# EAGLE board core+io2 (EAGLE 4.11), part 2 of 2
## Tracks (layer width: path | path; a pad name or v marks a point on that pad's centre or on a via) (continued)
N$113 (continued)
  Top 0.254: IC14.19 99.05,110.33 97.78,111.59 97.78,114.77 99.69,116.67 SV7.15
N$114  (via drill 0.61)
  Top 0.254: v96.52,102.07 97.15,102.7 97.15,116.67 SV7.13
  Bottom 0.254: v96.52,102.07 98.42,102.07 IC14.16
N$115  (via drill 0.61)
  Top 0.254: v100.96,118.58 103.5,121.12 106.67,121.12 v106.67,100.8
  Bottom 0.254: v100.96,118.58 95.24,118.58 94.61,117.94 SV7.11 | v106.67,100.8 102.23,100.8 101.59,100.16 100.32,100.16 IC14.15
N$116  (via drill 0.61)
  Top 0.254: v97.78,83.66 97.78,91.28 98.42,91.91 IC14.12 | v116.2,80.48 116.2,87.47 117.47,88.73 117.47,115.41 v116.83,116.04
  Bottom 0.254: v97.78,83.66 100.32,81.11 106.67,81.11 107.31,80.48 107.94,80.48 108.58,79.84 114.3,79.84 114.93,80.48 v116.2,80.48 | v116.83,116.04 116.2,116.67 106.67,116.67 106.04,116.04 92.7,116.04 92.07,116.67 SV7.9
N$117
  Top 0.254: IC14.2 91.44,110.33 90.16,111.59 90.16,116.04 90.8,116.67 90.8,117.94 92.07,119.22 SV7.10
N$118  (via drill 0.61)
  Top 0.254: v102.23,103.34 v102.23,111.59 | v95.88,113.5 95.88,117.94 95.24,118.58 95.24,119.85 SV7.12
  Bottom 0.254: v102.23,103.34 93.34,103.34 92.7,102.7 IC14.5 | v102.23,111.59 101.59,112.23 101.59,113.5 v95.88,113.5
N$119  (via drill 0.61)
  Top 0.254: v59.05,101.44 59.05,106.52 58.41,107.15 58.41,114.77 60.32,116.67 v60.32,122.39 | v85.72,123.03 88.26,125.56 97.15,125.56 97.15,120.48 SV7.14
  Bottom 0.254: v59.05,101.44 59.69,101.44 60.32,100.8 67.94,100.8 68.57,101.44 72.38,101.44 73.02,100.8 80.64,100.8 81.27,101.44 85.08,101.44 85.72,100.8 88.26,100.8 88.89,100.16 91.44,100.16 IC14.6 | v60.32,122.39 66.67,122.39 67.94,123.66 69.21,122.39 85.08,122.39 v85.72,123.03
N$120  (via drill 0.61)
  Top 0.254: v109.21,93.18 108.58,93.81 108.58,101.44 107.94,102.07 107.94,117.94 v108.58,118.58
  Bottom 0.254: v109.21,93.18 94.61,93.18 93.97,92.55 92.7,92.55 IC14.9 | v108.58,118.58 103.5,118.58 102.23,119.85 100.32,119.85 SV7.16
N$121  (via drill 0.61)
  Top 0.254: v85.72,118.58 85.72,113.5 85.08,112.86 85.08,92.55 v84.45,91.91
  Bottom 0.254: v85.72,118.58 88.89,118.58 89.53,119.22 SV7.8 | v84.45,91.91 80.64,91.91 IC13.9
N$122  (via drill 0.61)
  Top 0.254: v78.1,85.56 78.1,86.19 77.46,86.83 77.46,98.89 78.1,99.53 IC13.6 | v110.48,85.56 v110.48,123.03 | v86.99,123.03 86.99,120.48 SV7.6
  Bottom 0.254: v78.1,85.56 92.07,85.56 92.7,86.19 101.59,86.19 102.23,85.56 v110.48,85.56 | v110.48,123.03 107.94,123.03 107.31,122.39 87.62,122.39 v86.99,123.03
N$123
  Top 0.254: IC13.5 80,102.7 81.27,103.97 81.27,107.15 82.55,108.42 81.91,109.05 81.91,113.5 80.64,114.77 80.64,122.39 83.18,124.93 84.45,124.93 84.45,120.48 SV7.4
N$124  (via drill 0.61)
  Top 0.254: v56.51,50.63 56.51,36.03 55.24,34.76 52.7,34.76 51.43,36.03 51.43,36.66 50.8,37.3 50.8,39.2 50.16,39.84 v50.16,43.02 | v42.54,44.28 42.54,49.37 41.27,50.63 41.27,67.14 40,68.41 v40,70.32
  Bottom 0.254: v56.51,50.63 57.15,51.27 62.86,51.27 64.13,50 76.83,50 78.73,51.91 79.37,51.27 80.64,51.27 IC24.13 | v50.16,43.02 48.89,44.28 v42.54,44.28 | v40,70.32 45.72,70.32 46.98,69.05 47.62,69.05 IC26.5
N$125  (via drill 0.61)
  Top 0.254: v30.47,67.78 31.11,67.14 v31.11,46.19 | v79.37,46.82 80.64,48.09 80.64,48.73 IC24.14
  Bottom 0.254: v30.47,67.78 46.35,67.78 46.98,67.14 48.26,67.14 IC26.6 | v31.11,46.19 31.74,46.82 v79.37,46.82
N$126  (via drill 0.61)
  Top 0.254: v59.69,45.55 v59.69,57.62 | v50.8,57.62 50.8,63.34 50.16,63.97 IC26.7
  Bottom 0.254: v59.69,45.55 60.32,46.19 78.1,46.19 79.37,44.92 80,45.55 81.27,45.55 IC24.15 | v59.69,57.62 v50.8,57.62
N$127  (via drill 0.61)
  Top 0.254: v78.73,44.28 79.37,43.65 80.64,43.65 IC24.16 | v53.34,43.65 53.97,44.28 v53.97,63.97
  Bottom 0.254: v78.73,44.28 78.1,43.65 70.48,43.65 69.84,44.28 68.57,43.02 53.97,43.02 v53.34,43.65 | v53.97,63.97 53.34,63.34 52.07,63.34 50.8,62.06 49.53,62.06 IC26.8
N$128  (via drill 0.61)
  Top 0.254: v46.98,50.63 46.98,58.25 47.62,58.89 IC26.9 | v72.38,51.27 71.75,50.63 v71.75,41.11
  Bottom 0.254: v46.98,50.63 47.62,51.27 53.34,51.27 53.97,51.91 66.03,51.91 67.3,50.63 71.75,50.63 v72.38,51.27 | v71.75,41.11 80.64,41.11 IC24.17
N$129
  Bottom 0.254: IC25.3 68.57,74.77 67.3,76.03 67.3,77.94 78.1,77.94 79.37,76.67 80.64,76.67 IC24.3
N$130
  Bottom 0.254: IC25.4 70.48,71.59 71.75,72.86 78.73,72.86 80,74.13 80.64,74.13 IC24.4
N$131
  Bottom 0.254: IC25.5 70.48,69.05 71.75,70.32 79.37,70.32 80.64,71.59 IC24.5
N$132
  Bottom 0.254: IC25.6 70.48,66.51 71.75,67.78 79.37,67.78 80.64,69.05 IC24.6
N$133
  Bottom 0.254: IC25.7 70.48,63.97 71.75,62.7 83.18,62.7 83.81,63.34 83.81,65.88 82.55,65.88 IC24.7
N$134  (via drill 0.61)
  Top 0.254: v73.02,61.43 v73.02,65.24
  Bottom 0.254: v73.02,61.43 70.48,61.43 IC25.8 | v73.02,65.24 78.1,65.24 79.37,63.97 80.64,63.97 IC24.8
N$135
  Bottom 0.254: IC25.9 70.48,58.89 71.75,58.89 72.38,59.52 74.92,59.52 75.56,60.16 78.73,60.16 80,61.43 80.64,61.43 IC24.9
N$136  (via drill 0.61)
  Top 0.254: v43.81,39.2 43.81,49.37 v42.54,50.63 | v18.41,50.63 v18.41,81.75
  Bottom 0.254: v43.81,39.2 44.45,38.57 45.72,38.57 46.98,39.84 67.94,39.84 70.48,37.3 77.46,37.3 78.1,36.66 81.27,36.66 IC24.19 | v42.54,50.63 41.91,51.27 23.49,51.27 22.86,50.63 v18.41,50.63 | v18.41,81.75 19.68,83.02 29.84,83.02 30.47,82.39 41.27,82.39 41.91,83.02 45.72,83.02 48.89,79.84 IC26.1
N$137
  Bottom 0.254: IC25.1 70.48,79.21 74.29,79.21 75.56,80.48 83.18,80.48 84.45,79.21 95.88,79.21 IC24.39
N$138  (via drill 0.61)
  Top 0.254: v92.07,81.11 92.07,71.59 92.7,70.95 92.7,40.48 90.8,38.57 90.8,37.3 91.44,36.66 91.44,24.6 v90.8,23.96 | v99.69,23.96 99.69,16.98 100.32,16.34 v100.32,11.9
  Bottom 0.254: v92.07,81.11 92.7,81.75 95.88,81.75 IC24.40 | v99.69,23.96 v90.8,23.96 | v100.32,11.9 108.58,11.9 109.21,11.27 113.02,11.27 113.66,11.9 118.1,11.9 119.38,13.17 121.28,13.17 IC27.9
N$140
  Top 0.254: IC27.8 123.82,10.63 124.45,10.63 C4.1 | IC27.12 123.19,20.15 129.53,13.81 129.53,13.17 R4.1
  Bottom 0.254: R4.1 129.53,13.17 126.99,10.63 125.72,10.63 C4.1
N$141
  Top 0.254: R3.1 128.27,20.79 129.53,20.79 R4.2
  Bottom 0.254: IC27.13 123.19,22.7 123.82,22.06 125.72,22.06 126.99,20.79 R3.1
N$142
  Bottom 0.254: IC27.11 123.82,18.25 132.07,18.25 C5.1
N$143
  Bottom 0.254: R10.1 114.3,5.55 113.02,6.82 112.39,6.82 R11.E
N$144  (via drill 0.61)
  Top 0.254: v86.35,16.34 86.35,18.88 86.99,19.52 88.89,19.52 88.89,20.15 X1.4
  Bottom 0.254: v86.35,16.34 94.61,16.34 95.88,17.61 X1.6
N$145
  Top 0.254: X1.8 91.44,18.25 92.7,18.25 X1.7
N$146
  Bottom 0.254: 90.8,19.52 102.23,19.52 X1.G1 | 90.8,19.52 87.62,19.52 86.99,20.15 X1.5 | 90.8,19.52 90.8,21.42 88.89,23.33 83.81,23.33 81.27,20.79 X1.G2
N$147  (via drill 0.61)
  Top 0.254: IC18.13 153.03,20.15 153.03,18.88 IC18.12 | v100.96,34.76 100.96,36.66 99.05,38.57 99.05,53.17 100.32,54.45 100.32,60.8 100.96,61.43 IC21.5 | v149.85,32.22 v149.85,20.79
  Bottom 0.254: v100.96,34.76 110.48,34.76 112.39,36.66 122.55,36.66 125.72,33.49 125.72,31.58 146.04,31.58 146.68,32.22 v149.85,32.22 | v149.85,20.79 151.76,20.79 IC18.13
N$148
  Top 0.254: IC18.11 154.3,15.71 154.94,15.71 LED1.K
N$149
  Bottom 0.254: R12.1 125.72,20.79 126.99,19.52 154.94,19.52 158.11,16.34 LED1.A
N$150  (via drill 0.61)
  Top 0.254: v118.74,77.94 118.74,71.59 IC21.24 | v123.19,71.59 123.19,67.78 123.82,67.14 123.82,46.82 123.19,46.19 123.19,42.38 125.09,40.48 125.09,23.96 R13.2
  Bottom 0.254: v118.74,77.94 v113.66,77.94 112.39,79.21 106.04,79.21 JP2.1 | v123.19,71.59 118.74,71.59 IC21.24
N$151
  Bottom 0.254: IC18.8 151.76,8.09 150.49,9.36 144.14,9.36 143.5,10 143.5,14.44 158.75,14.44 163.19,18.88 163.19,63.97 158.11,63.97 156.84,62.7 150.49,62.7 149.22,61.43 IC28.4
N$152
  Top 0.254: IC19.5 148.59,36.66 152.39,40.48 152.39,45.55 157.47,50.63 157.47,64.61 156.2,65.88 IC28.15
N$153
  Top 0.254: IC20.7 118.1,30.31 119.38,30.31 IC20.8
N$154
  Bottom 0.254: C7.1 109.85,25.23 112.39,22.7 113.02,22.7 114.3,21.42 IC27.3
N$155
  Top 0.254: IC20.5 113.02,31.58 118.1,36.66 121.91,36.66 121.91,38.57 C9.2
N$156
  Bottom 0.254: IC20.4 110.48,31.58 112.39,33.49 121.91,33.49 C9.1
N$157  (via drill 0.61)
  Top 0.254: v106.67,36.03 106.67,31.58 IC20.3
  Bottom 0.254: v106.67,36.03 100.32,36.03 C8.2
N$158
  Top 0.254: C8.1 100.32,30.95 101.59,30.95 IC20.1
N$159
  Bottom 0.254: C11.1 110.48,28.41 111.12,29.04 113.02,29.04 114.3,30.31 IC20.6
N$160
  Top 0.254: C10.2 102.86,28.41 104.13,29.68 104.13,30.31 IC20.2
NMI\  (via drill 0.61)
  Top 0.254: IC17.6 126.36,69.05 125.09,70.32 125.09,73.5 R6.1 | v114.93,55.71 v114.93,67.78
  Bottom 0.254: v114.93,55.71 102.86,55.71 IC21.7 | v114.93,67.78 121.91,67.78 123.19,69.05 126.36,69.05 IC17.6
OUT00  (via drill 0.61)
  Top 0.254: v10.79,86.83 10.79,88.73 IC6.11 | v28.57,87.47 28.57,82.39 IC1.1
  Bottom 0.254: v10.79,86.83 11.43,87.47 v28.57,87.47
OUT01  (via drill 0.61)
  Top 0.254: v25.39,79.21 23.49,81.11 23.49,88.73 IC7.11
  Bottom 0.254: v25.39,79.21 27.3,79.21 IC1.2
OUT02
  Bottom 0.254: IC1.3 27.3,76.67 26.66,76.03 22.86,76.03 22.22,75.4 14.6,75.4 6.98,83.02 5.08,83.02 1.27,86.83 1.27,90.64 33.65,90.64 34.92,89.37 IC8.11
OUT03  (via drill 0.61)
  Top 0.254: v30.47,87.47 30.47,74.77 29.84,74.13 IC1.4
  Bottom 0.254: v30.47,87.47 42.54,87.47 44.45,89.37 47.62,89.37 IC10.11
OUT04  (via drill 0.61)
  Top 0.254: v25.39,71.59 25.39,77.94 22.86,80.48 22.86,83.02 v20.31,85.56 | v59.69,84.29 61.59,86.19 61.59,88.73 IC11.11
  Bottom 0.254: v25.39,71.59 27.3,71.59 IC1.5 | v20.31,85.56 20.95,84.92 21.58,84.92 22.22,85.56 31.11,85.56 31.74,86.19 42.54,86.19 43.18,85.56 56.51,85.56 57.78,84.29 v59.69,84.29
OUT05  (via drill 0.61)
  Top 0.254: v43.18,93.18 43.18,83.66 41.27,81.75 v41.27,69.05
  Bottom 0.254: v43.18,93.18 55.88,93.18 55.88,91.28 56.51,90.64 57.15,90.64 57.78,91.28 59.69,91.28 60.32,90.64 68.57,90.64 69.84,89.37 73.02,89.37 IC12.11 | v41.27,69.05 40.64,68.41 31.11,68.41 30.47,69.05 29.84,69.05 IC1.6
OUT06  (via drill 0.61)
  Top 0.254: v86.35,60.16 86.35,84.29 86.99,84.92 86.99,88.73 IC13.11 | v80,60.16 79.37,59.52 v79.37,52.54 | v33.65,54.45 33.65,38.57 32.38,37.3 30.47,37.3 30.47,45.55 29.84,46.19 29.84,46.82 30.47,47.46 30.47,66.51 29.84,66.51 IC1.7
  Bottom 0.254: v80,60.16 v86.35,60.16 | v79.37,52.54 78.73,53.17 52.7,53.17 52.07,52.54 40.64,52.54 38.73,54.45 v33.65,54.45
OUT07  (via drill 0.61)
  Top 0.254: v33.02,63.97 33.65,64.61 33.65,79.84 v33.02,80.48 | v46.98,80.48 v46.98,87.47
  Bottom 0.254: v33.02,63.97 29.84,63.97 IC1.8 | v33.02,80.48 33.02,81.11 41.91,81.11 42.54,80.48 v46.98,80.48 | v46.98,87.47 47.62,86.83 56.51,86.83 57.15,87.47 57.78,87.47 59.05,86.19 61.59,86.19 62.23,85.56 72.38,85.56 73.66,86.83 78.1,86.83 78.73,86.19 81.91,86.19 83.18,87.47 92.7,87.47 94.61,89.37 98.42,89.37 IC14.11
PIA-A0  (via drill 0.61)
  Top 0.254: v72.38,80.48 v72.38,74.13 | IC6.3 1.9,107.15 1.27,106.52 1.27,36.66 1.9,36.03 IC2.2 4.44,36.03 5.08,36.66 v5.08,45.55 | v13.97,46.19 13.97,36.66 14.6,36.03 IC3.2 | v52.7,80.48 52.7,86.19 52.07,86.83 52.07,106.52 52.7,107.15 IC11.3 | v27.93,46.19 27.3,45.55 27.3,41.11 26.66,40.48 26.66,36.66 27.3,36.03 IC4.2
  Bottom 0.254: IC4.2 29.84,36.03 31.74,36.03 33.02,34.76 37.46,34.76 38.73,36.03 40,36.03 IC9.2 42.54,36.03 44.45,36.03 45.08,35.39 46.98,35.39 47.62,34.76 52.7,34.76 53.34,35.39 IC15.2 55.24,36.03 57.15,36.03 57.78,35.39 59.69,35.39 60.32,34.76 65.4,34.76 66.03,35.39 IC16.2 | v72.38,74.13 75.56,74.13 IC25.18 | v72.38,80.48 71.75,81.11 62.86,81.11 | 62.86,81.11 61.59,79.84 SV9.1 | 80.64,105.88 80,106.52 IC13.3 | 80.64,105.88 88.26,105.88 89.53,107.15 90.8,107.15 IC14.3 | IC6.3 3.8,106.52 4.44,105.88 12.06,105.88 12.7,106.52 13.33,106.52 13.97,107.15 14.6,107.15 IC7.3 17.14,107.15 19.04,107.15 19.68,106.52 21.58,106.52 22.22,105.88 27.3,105.88 27.93,106.52 IC8.3 29.84,107.15 33.65,107.15 34.92,105.88 37.46,105.88 38.1,106.52 40.64,106.52 IC10.3 42.54,107.15 44.45,107.15 45.08,106.52 46.98,106.52 47.62,105.88 52.7,105.88 53.34,106.52 IC11.3 55.24,107.15 57.15,107.15 57.78,106.52 59.69,106.52 60.32,105.88 65.4,105.88 66.03,106.52 IC12.3 67.94,107.15 69.84,107.15 71.11,105.88 80.64,105.88 | 13.33,45.55 v13.97,46.19 | v5.08,45.55 13.33,45.55 | 62.86,81.11 55.88,81.11 55.24,80.48 v52.7,80.48 | v27.93,46.19 27.3,45.55 13.33,45.55
PIA-A1  (via drill 0.61)
  Top 0.254: v74.92,84.29 74.92,72.22 75.56,71.59 IC25.17 | v60.96,84.29 60.32,83.66 60.32,77.3 60.96,76.67 SV9.3 | v87.62,84.29 87.62,87.47 88.89,88.73 88.89,98.26 89.53,98.89 89.53,103.34 90.8,104.61 IC14.4 | v72.38,27.14 72.38,39.2 73.66,40.48 73.66,55.08 73.02,55.71 73.02,60.16 71.75,61.43 v71.75,71.59
  Bottom 0.254: IC2.5 3.8,27.77 4.44,27.14 12.06,27.14 12.7,27.77 13.33,27.77 13.97,28.41 14.6,28.41 IC3.5 16.5,27.77 21.58,27.77 22.22,27.14 24.76,27.14 25.39,27.77 27.93,27.77 IC4.5 29.2,27.77 34.29,27.77 34.92,27.14 37.46,27.14 38.1,27.77 38.73,27.77 39.37,28.41 40,28.41 IC9.5 41.91,27.77 46.98,27.77 47.62,27.14 50.16,27.14 50.8,27.77 51.43,27.77 52.07,28.41 52.7,28.41 IC15.5 54.61,27.77 59.69,27.77 60.32,27.14 62.86,27.14 63.5,27.77 66.03,27.77 IC16.5 67.3,27.77 70.48,27.77 71.11,27.14 v72.38,27.14 | IC6.4 3.8,103.97 4.44,103.34 12.06,103.34 13.33,104.61 14.6,104.61 IC7.4 16.5,103.97 17.14,103.34 24.76,103.34 26.03,104.61 27.3,104.61 IC8.4 29.2,103.97 29.84,103.34 37.46,103.34 38.73,104.61 40,104.61 IC10.4 41.91,103.97 42.54,103.34 50.16,103.34 51.43,104.61 52.7,104.61 IC11.4 54.61,103.97 55.24,103.34 62.86,103.34 64.13,104.61 65.4,104.61 IC12.4 67.3,103.97 67.94,103.34 75.56,103.34 76.83,104.61 78.1,104.61 IC13.4 80.64,104.61 82.55,104.61 83.81,103.34 90.8,103.34 91.44,103.97 IC14.4 | v60.96,84.29 v74.92,84.29 75.56,83.66 86.99,83.66 v87.62,84.29 | v71.75,71.59 75.56,71.59 IC25.17
PIA-A2
  Top 0.254: SV9.5 61.59,73.5 60.32,72.22 60.32,70.95 60.96,70.32 65.4,70.32 65.4,88.1 64.77,88.73 64.77,95.08 66.03,96.36 IC12.7 | IC25.16 77.46,69.69 78.73,70.95 78.73,76.03 79.37,76.67 79.37,81.11 80,81.75 80,87.47 81.27,88.73 81.27,95.08 80,96.36 IC13.7 | IC4.6 27.93,26.5 26.66,27.77 26.66,35.39 26.03,36.03 26.03,70.95 26.66,71.59 26.66,95.08 27.93,96.36 IC8.7
  Bottom 0.254: IC16.6 65.4,25.87 64.13,24.6 56.51,24.6 55.24,25.87 IC15.6 52.7,25.87 51.43,24.6 45.72,24.6 44.45,25.87 42.54,25.87 IC9.6 40,25.87 38.73,24.6 33.65,24.6 33.02,25.23 29.2,25.23 IC4.6 27.3,25.87 26.03,25.87 24.76,24.6 13.33,24.6 | 13.33,24.6 5.71,24.6 4.44,25.87 IC2.6 | 13.33,24.6 14.6,25.87 IC3.6 | IC6.7 4.44,96.99 5.71,95.72 13.33,95.72 14.6,96.99 IC7.7 17.14,96.99 17.77,96.36 21.58,96.36 22.22,95.72 24.76,95.72 26.03,96.99 27.3,96.99 IC8.7 29.84,96.99 30.47,96.36 34.29,96.36 34.92,95.72 37.46,95.72 38.73,96.99 40,96.99 IC10.7 42.54,96.99 43.18,96.36 46.98,96.36 47.62,95.72 50.16,95.72 51.43,96.99 52.7,96.99 IC11.7 55.24,96.99 56.51,95.72 62.86,95.72 63.5,96.36 66.03,96.36 IC12.7 67.94,96.99 68.57,96.36 72.38,96.36 73.02,95.72 75.56,95.72 76.19,96.36 78.73,96.36 IC13.7 80,96.36 82.55,96.36 83.18,95.72 88.26,95.72 88.89,96.36 90.16,96.36 90.8,96.99 IC14.7
PIA-A3  (via drill 0.61)
  Top 0.254: v72.38,93.18 72.38,85.56 74.29,83.66 74.29,71.59 74.92,70.95 74.92,67.14 75.56,66.51 IC25.15 | v63.5,93.18 63.5,88.73 62.86,88.1 v62.86,82.39 62.86,72.22 62.23,71.59 SV9.7 | v50.8,81.75 50.8,78.58 50.16,77.94 46.98,77.94 46.98,79.21 45.72,80.48 v45.72,94.45 | IC9.9 42.54,18.25 43.81,16.98 v43.81,15.71 42.54,14.44 42.54,6.18 40.64,4.28 40.64,3.01 40,2.38 34.29,2.38 34.29,3.01 v33.65,3.64 | v7.62,16.98 8.25,17.61 8.25,27.14 8.89,27.77 8.89,39.2 10.16,40.48 10.16,41.74 10.79,42.38 10.79,47.46 13.33,50 13.33,53.81 12.7,54.45 12.7,68.41 13.33,69.05 13.33,69.69 12.7,70.32 12.7,79.84 13.33,80.48 v13.33,93.81 | v22.22,3.64 22.22,11.9 20.31,13.81 v20.31,16.98
  Bottom 0.254: 62.86,93.18 60.32,93.18 59.69,93.81 54.61,93.81 IC11.8 | 62.86,93.18 64.13,94.45 65.4,94.45 IC12.8 67.94,94.45 69.84,94.45 71.11,93.18 v72.38,93.18 78.1,93.18 78.73,93.81 IC13.8 80.64,94.45 81.91,94.45 83.18,93.18 90.8,93.18 91.44,93.81 IC14.8 | v63.5,93.18 62.86,93.18 | v62.86,82.39 51.43,82.39 v50.8,81.75 | v45.72,94.45 42.54,94.45 IC10.8 40.64,93.81 40,93.18 31.74,93.18 30.47,94.45 29.84,94.45 IC8.8 27.93,93.81 27.3,93.18 19.04,93.18 17.77,94.45 17.14,94.45 IC7.8 14.6,94.45 13.33,94.45 12.7,93.81 | v43.81,15.71 44.45,16.34 45.72,16.34 46.35,16.98 50.16,16.98 51.43,18.25 52.7,18.25 IC15.9 55.24,18.25 57.15,18.25 57.78,17.61 59.69,17.61 60.32,16.98 65.4,16.98 66.03,17.61 IC16.9 | IC2.9 3.8,17.61 4.44,16.98 v7.62,16.98 12.06,16.98 12.7,17.61 13.33,17.61 13.97,18.25 14.6,18.25 IC3.9 17.14,18.25 19.04,18.25 19.68,17.61 20.31,17.61 | 20.31,17.61 21.58,17.61 22.22,16.98 27.3,16.98 27.93,17.61 IC4.9 | 12.7,93.81 12.06,93.18 6.34,93.18 5.71,93.81 3.8,93.81 IC6.8 | v13.33,93.81 12.7,93.81 | v33.65,3.64 33.02,3.01 22.86,3.01 v22.22,3.64 | 20.31,17.61 v20.31,16.98
PIA-A4  (via drill 0.61)
  Top 0.254: v71.11,94.45 71.11,93.18 71.75,92.55 71.75,84.92 73.66,83.02 73.66,70.95 74.29,70.32 74.29,66.51 74.92,65.88 74.92,64.61 75.56,63.97 IC25.14 | v65.4,65.24 65.4,67.78 63.5,67.78 62.23,69.05 SV9.9 | v6.98,22.06 7.62,22.7 7.62,27.77 8.25,28.41 8.25,39.84 9.52,41.11 9.52,42.38 10.16,43.02 10.16,78.58 8.89,79.84 8.89,93.81 9.52,94.45 IC6.13
  Bottom 0.254: IC12.13 74.92,95.08 76.19,95.08 76.83,95.72 81.91,95.72 82.55,95.08 86.35,95.08 IC13.13 87.62,95.08 88.89,95.08 89.53,95.72 93.34,95.72 94.61,94.45 98.42,94.45 IC14.13 | IC12.13 73.66,95.08 72.38,95.08 71.75,95.72 64.13,95.72 63.5,95.08 62.23,95.08 IC11.13 60.32,94.45 56.51,94.45 55.24,95.72 51.43,95.72 50.8,95.08 49.53,95.08 IC10.13 48.26,95.08 46.98,95.08 46.35,95.72 38.73,95.72 38.1,95.08 36.83,95.08 IC8.13 35.55,95.08 34.29,95.08 33.65,95.72 26.03,95.72 25.39,95.08 24.12,95.08 IC7.13 22.86,95.08 21.58,95.08 20.95,95.72 14.6,95.72 13.97,95.08 11.43,95.08 IC6.13 | v71.11,94.45 73.02,94.45 IC12.13 | v65.4,65.24 70.48,65.24 71.11,64.61 72.38,64.61 73.02,63.97 75.56,63.97 IC25.14 | IC16.12 73.66,18.88 71.75,18.88 71.11,19.52 65.4,19.52 64.77,18.88 62.23,18.88 IC15.12 60.32,18.25 58.41,18.25 57.78,18.88 55.88,18.88 55.24,19.52 50.16,19.52 49.53,18.88 IC9.12 47.62,18.25 46.35,18.25 45.08,16.98 40,16.98 38.73,18.25 37.46,18.25 IC4.12 34.92,18.25 33.02,18.25 32.38,18.88 30.47,18.88 29.84,19.52 27.3,19.52 26.66,18.88 24.12,18.88 IC3.12 22.22,18.25 20.31,18.25 19.04,19.52 13.97,19.52 | 13.97,19.52 12.7,18.25 12.06,18.25 IC2.12 | 13.97,19.52 12.7,20.79 12.7,22.06 v6.98,22.06
PIA-A5  (via drill 0.61)
  Top 0.254: v71.75,60.16 72.38,59.52 v72.38,55.08 | v37.46,56.98 37.46,53.17 38.1,52.54 38.1,32.85 37.46,32.22 38.1,31.58 38.1,26.5 37.46,25.87 IC4.15 | v59.69,66.51 59.05,65.88 59.05,63.97 57.78,62.7 54.61,62.7 54.61,43.65 53.34,42.38 52.7,42.38 v52.07,43.02 | v69.84,43.02 65.4,47.46 65.4,54.45 v66.03,55.08 | v33.65,56.35 33.65,63.34 34.29,63.97 34.29,80.48 33.65,81.11 33.65,95.72 34.92,96.99 IC8.14
  Bottom 0.254: IC14.14 99.05,97.62 93.97,97.62 93.34,98.26 88.26,98.26 87.62,97.62 IC13.14 85.72,96.99 81.91,96.99 80.64,98.26 78.1,98.26 76.83,96.99 75.56,96.99 IC12.14 73.02,96.99 69.21,96.99 67.94,98.26 65.4,98.26 64.13,96.99 62.86,96.99 IC11.14 60.32,96.99 56.51,96.99 55.24,98.26 52.07,98.26 51.43,97.62 49.53,97.62 IC10.14 47.62,96.99 45.72,96.99 44.45,98.26 40,98.26 39.37,97.62 36.83,97.62 IC8.14 34.92,96.99 31.11,96.99 29.84,98.26 24.76,98.26 24.12,97.62 IC7.14 22.22,96.99 18.41,96.99 17.14,98.26 14.6,98.26 13.97,97.62 11.43,97.62 IC6.14 | IC16.15 73.02,25.87 71.11,25.87 69.84,27.14 64.13,27.14 63.5,26.5 62.23,26.5 IC15.15 60.96,26.5 59.69,26.5 59.05,27.14 51.43,27.14 50.8,26.5 49.53,26.5 IC9.15 48.26,26.5 46.98,26.5 46.35,27.14 38.73,27.14 38.1,26.5 36.83,26.5 IC4.15 34.92,25.87 33.02,25.87 31.74,27.14 26.03,27.14 25.39,26.5 24.12,26.5 IC3.15 22.86,26.5 21.58,26.5 20.95,27.14 13.33,27.14 12.7,26.5 11.43,26.5 IC2.15 | v71.75,60.16 74.29,60.16 74.92,60.8 76.19,60.8 IC25.13 | v72.38,55.08 71.75,54.45 66.03,54.45 | 66.03,54.45 48.26,54.45 45.08,57.62 38.1,57.62 v37.46,56.98 36.19,56.98 35.55,56.35 v33.65,56.35 | v59.69,66.51 60.96,66.51 SV9.11 | v52.07,43.02 52.7,43.02 53.34,42.38 69.21,42.38 v69.84,43.02 | 66.03,54.45 v66.03,55.08
PIA-A6  (via drill 0.61)
  Top 0.254: v63.5,98.26 63.5,100.8 | 63.5,100.8 63.5,103.97 62.86,104.61 IC11.17 | v45.72,104.61 v45.72,100.8 | v69.84,104.61 69.84,102.7 67.94,100.8 63.5,100.8 | v20.31,104.61 20.95,103.97 v20.95,100.8 | v62.86,57.62 62.86,62.06 62.23,62.7 61.59,62.7 61.59,63.34 SV9.13 | v96.52,84.92 95.88,85.56 95.88,100.16 97.78,102.07 97.78,103.97 98.42,104.61 IC14.17 | v88.89,84.29 86.99,82.39 86.99,60.8 87.62,60.16 v87.62,57.62 | v70.48,29.68 70.48,41.11 71.11,41.74 v71.11,57.62 | v32.38,29.04 32.38,32.85 33.02,33.49 33.02,36.66 34.29,37.94 34.29,50 34.92,50.63 34.92,56.35 34.29,56.98 34.29,62.7 34.92,63.34 34.92,81.11 34.29,81.75 34.29,95.08 34.92,95.72 37.46,95.72 38.1,96.36 38.1,103.97 37.46,104.61 IC8.17
  Bottom 0.254: IC6.17 11.43,105.25 12.7,105.25 13.33,105.88 20.95,105.88 21.58,105.25 22.86,105.25 IC7.17 22.22,104.61 v20.31,104.61 | IC8.17 36.83,105.25 38.1,105.25 38.73,105.88 46.35,105.88 46.98,105.25 48.26,105.25 IC10.17 47.62,104.61 v45.72,104.61 | v63.5,98.26 57.15,98.26 55.88,99.53 55.88,100.8 v45.72,100.8 v20.95,100.8 | v69.84,104.61 73.02,104.61 IC12.17 | IC2.16 12.06,28.41 12.7,28.41 13.97,29.68 17.14,29.68 18.41,28.41 22.22,28.41 IC3.16 24.76,28.41 26.03,28.41 27.3,29.68 29.84,29.68 30.47,29.04 | 30.47,29.04 31.11,28.41 34.92,28.41 IC4.16 37.46,28.41 38.1,28.41 39.37,29.68 42.54,29.68 43.81,28.41 47.62,28.41 IC9.16 50.16,28.41 50.8,28.41 52.07,29.68 55.24,29.68 56.51,28.41 60.32,28.41 IC15.16 62.86,28.41 64.13,28.41 65.4,29.68 67.94,29.68 | 67.94,29.68 69.21,28.41 73.02,28.41 IC16.16 | IC13.17 87.62,105.25 90.16,105.25 90.8,105.88 93.34,105.88 94.61,104.61 98.42,104.61 IC14.17 | 70.48,57.62 71.11,58.25 72.38,58.25 73.02,58.89 75.56,58.89 IC25.12 78.1,58.89 79.37,58.89 80.64,57.62 v87.62,57.62 | 70.48,57.62 v62.86,57.62 | v96.52,84.92 89.53,84.92 v88.89,84.29 | 67.94,29.68 v70.48,29.68 | v71.11,57.62 70.48,57.62 | 30.47,29.04 v32.38,29.04
PIA-A7  (via drill 0.61)
  Top 0.254: v77.46,36.03 77.46,50.63 76.83,51.27 76.83,55.71 IC25.11 78.1,56.35 78.73,56.98 78.73,62.7 79.37,63.34 79.37,72.22 v80,72.86 | v52.07,62.06 52.07,47.46 46.98,42.38 46.98,36.66 47.62,36.03 IC9.19 | v71.11,107.15 71.11,110.96 v70.48,111.59 v70.48,113.5 | v64.13,109.69 v64.13,107.15 | v88.26,116.04 87.62,115.41 v87.62,114.14 | v100.32,72.86 100.32,87.47 101.59,88.73 101.59,102.7 100.96,103.34 101.59,103.97 101.59,106.52 100.96,107.15 IC14.18
  Bottom 0.254: IC2.19 12.06,36.03 13.33,36.03 14.6,37.3 17.77,37.3 19.04,36.03 22.22,36.03 IC3.19 24.12,36.66 24.76,37.3 29.84,37.3 30.47,36.66 32.38,36.66 33.02,36.03 34.92,36.03 IC4.19 36.83,36.66 39.37,36.66 40,37.3 43.18,37.3 43.81,36.66 45.08,36.66 45.72,36.03 47.62,36.03 IC9.19 49.53,36.66 51.43,36.66 52.07,37.3 55.24,37.3 55.88,36.66 57.78,36.66 58.41,36.03 60.32,36.03 IC15.19 62.86,36.03 64.13,36.03 65.4,37.3 69.21,37.3 69.84,36.66 73.66,36.66 IC16.19 75.56,36.03 v77.46,36.03 | v52.07,62.06 52.7,62.7 57.78,62.7 59.05,61.43 60.96,61.43 SV9.15 | IC13.18 87.62,107.78 90.16,107.78 90.8,108.42 93.97,108.42 95.24,107.15 98.42,107.15 IC14.18 100.32,107.78 103.5,110.96 106.04,110.96 106.67,111.59 106.67,112.86 106.04,113.5 103.5,113.5 101.59,115.41 88.89,115.41 v88.26,116.04 | IC6.18 12.06,107.15 12.7,107.15 13.97,108.42 17.14,108.42 17.77,107.78 19.68,107.78 20.31,107.15 22.22,107.15 IC7.18 24.12,107.78 24.76,108.42 29.84,108.42 30.47,107.78 35.55,107.78 IC8.18 37.46,107.15 38.73,107.15 40,108.42 42.54,108.42 43.18,107.78 45.08,107.78 45.72,107.15 47.62,107.15 IC10.18 50.16,107.15 51.43,107.15 52.7,108.42 55.24,108.42 55.88,107.78 57.78,107.78 58.41,107.15 60.32,107.15 IC11.18 62.86,107.15 v64.13,107.15 | v71.11,107.15 73.02,107.15 IC12.18 | v70.48,111.59 68.57,111.59 67.94,110.96 65.4,110.96 v64.13,109.69 | v87.62,114.14 86.99,113.5 85.72,113.5 85.08,112.86 82.55,112.86 81.91,113.5 v70.48,113.5 | v80,72.86 v100.32,72.86
PIA-B0  (via drill 0.61)
  Top 0.254: v58.41,77.94 58.41,74.77 57.78,74.13 IC26.18
  Bottom 0.254: IC5.23 22.22,79.21 24.12,79.21 25.39,80.48 29.84,80.48 31.11,79.21 42.54,79.21 IC1.23 45.08,79.21 45.72,79.21 46.98,77.94 v58.41,77.94 63.5,77.94 64.13,78.58 SV9.2
PIA-B1  (via drill 0.61)
  Top 0.254: v54.61,75.4 54.61,72.22 55.24,71.59 IC26.17
  Bottom 0.254: IC5.22 22.22,76.67 24.12,76.67 25.39,77.94 29.84,77.94 31.11,76.67 42.54,76.67 IC1.22 45.08,76.67 45.72,76.67 46.98,75.4 v54.61,75.4 63.5,75.4 64.13,76.03 SV9.4
PIA-B2  (via drill 0.61)
  Top 0.254: v58.41,72.86 58.41,69.69 57.78,69.05 IC26.16
  Bottom 0.254: IC5.21 22.22,74.13 24.12,74.13 25.39,75.4 29.84,75.4 31.11,74.13 42.54,74.13 IC1.21 45.08,74.13 45.72,74.13 46.98,72.86 v58.41,72.86 63.5,72.86 64.13,73.5 SV9.6
PIA-B3
  Bottom 0.254: IC5.20 22.22,71.59 23.49,72.86 37.46,72.86 38.73,71.59 42.54,71.59 IC1.20 45.08,71.59 45.72,71.59 46.98,70.32 51.43,70.32 | 51.43,70.32 55.24,66.51 IC26.15 | 51.43,70.32 62.23,70.32 63.5,71.59 SV9.8
PIA-B4  (via drill 0.61)
  Top 0.254: v58.41,67.78 58.41,64.61 57.78,63.97 IC26.14 | v22.86,51.91 22.86,53.81 23.49,54.45 23.49,65.24 22.22,66.51 IC5.18 | v67.3,51.91 67.3,56.98 67.94,57.62 67.3,58.25 v67.3,67.78
  Bottom 0.254: 63.5,67.78 v58.41,67.78 | 63.5,67.78 64.13,68.41 SV9.10 | v22.86,51.91 52.7,51.91 53.34,52.54 66.67,52.54 v67.3,51.91 | v67.3,67.78 63.5,67.78
PIA-B5
  Bottom 0.254: 46.35,65.24 45.08,66.51 IC1.18 | 46.35,65.24 62.23,65.24 63.5,66.51 SV9.12 | 46.35,65.24 26.66,65.24 26.66,63.34 27.3,62.7 29.84,62.7 32.38,60.16 53.97,60.16 55.24,61.43 IC26.13
PIA-B6  (via drill 0.61)
  Top 0.254: v59.69,58.89 v59.69,62.7
  Bottom 0.254: v59.69,58.89 57.78,58.89 IC26.12 | v59.69,62.7 63.5,62.7 64.13,63.34 SV9.14
PIA-B7  (via drill 0.61)
  Top 0.254: v58.41,60.16 58.41,56.98 57.78,56.35 IC26.11
  Bottom 0.254: v58.41,60.16 63.5,60.16 64.13,60.8 SV9.16
R/W\  (via drill 0.61)
  Top 0.254: v100.32,33.49 98.42,33.49 IC24.21 | v108.58,33.49 v108.58,43.65 | v132.07,66.51 132.07,59.52 131.44,58.89 v131.44,44.28 | v128.27,84.92 v128.27,118.58 | v140.33,84.92 140.33,67.78 v139.69,67.14
  Bottom 0.254: v100.32,33.49 v108.58,33.49 | v108.58,43.65 116.2,43.65 IC21.13 118.74,43.65 121.28,43.65 122.55,44.92 130.81,44.92 v131.44,44.28 | v132.07,66.51 139.69,66.51 | 139.69,66.51 141.6,66.51 IC17.34 | v128.27,118.58 121.28,118.58 120.64,117.94 IC22.27 | v128.27,84.92 128.9,84.29 139.69,84.29 v140.33,84.92 | 139.69,66.51 v139.69,67.14
RST\  (via drill 0.61)
  Top 0.254: v161.28,11.9 161.28,13.17 163.19,15.08 163.19,70.95 161.28,72.86 v161.28,81.75 | v95.24,77.94 95.24,67.14 95.88,66.51 IC24.34 | v111.12,75.4 v111.12,77.94
  Bottom 0.254: v161.28,11.9 146.68,11.9 146.04,11.27 IC18.6 | v161.28,81.75 144.14,81.75 IC17.40 142.23,82.39 130.81,82.39 128.9,80.48 123.82,80.48 118.74,75.4 114.3,75.4 113.66,74.77 111.12,74.77 v111.12,75.4 | v95.24,77.94 102.86,77.94 v111.12,77.94
RX  (via drill 0.61)
  Top 0.254: v112.39,52.54 113.02,51.91 113.02,39.2 IC20.12 | v105.41,52.54 105.41,68.41 v106.04,69.05
  Bottom 0.254: v112.39,52.54 v105.41,52.54 | v106.04,69.05 103.5,69.05 IC21.2
RXD
  Top 0.254: IC20.13 109.85,37.3 109.85,33.49 108.58,32.22 108.58,27.77 105.41,24.6 100.32,24.6 100.32,27.14 97.78,29.68 95.88,29.68 95.88,22.06 95.24,21.42 X1.2
TX  (via drill 0.61)
  Top 0.254: v113.66,57.62 113.66,39.84 114.3,39.2 IC20.11
  Bottom 0.254: v113.66,57.62 113.02,58.25 102.86,58.25 IC21.6
TXD  (via drill 0.61)
  Top 0.254: v92.07,37.3 92.07,21.42 X1.3
  Bottom 0.254: v92.07,37.3 100.32,37.3 100.96,36.66 106.04,36.66 106.67,37.3 107.31,37.3 IC20.14
VCC  (via drill 0.61)
  Top 0.508: v10.79,115.41 10.79,112.86 IC6.20 | v50.16,114.77 48.89,113.5 48.89,112.86 IC10.20 | v61.59,114.77 61.59,112.86 IC11.20 | v22.86,115.41 22.22,114.77 22.22,112.23 IC7.20 | v27.93,122.39 v27.93,116.67 | v36.19,122.39 36.19,112.86 IC8.20 | IC23.27 160.65,117.94 160.65,119.22 IC23.28 | IC29.27 140.33,117.94 140.33,119.22 IC29.28 | IC14.20 100.96,112.23 102.23,113.5 102.23,118.58 103.5,119.85 IC22.1 | v69.84,114.77 70.48,115.41 70.48,117.94 71.11,118.58 74.92,118.58 75.56,117.94 75.56,112.23 IC12.20 | v130.17,69.05 130.17,65.24 128.9,63.97 IC17.8 | IC17.36 142.87,70.95 142.87,69.69 IC17.35 | v151.76,71.59 v151.76,69.05 | R6.2 117.47,74.77 117.47,76.03 R8.2 117.47,77.3 117.47,78.58 R5.2 | v114.93,79.21 114.93,81.11 R7.2 | v122.55,63.97 122.55,70.32 121.91,70.95 v121.91,74.13 | v48.89,43.02 48.89,39.2 IC9.20 | v36.19,42.38 36.19,39.2 IC4.20 | v13.97,79.21 13.33,79.21 13.33,70.95 v13.97,70.32 13.97,68.41 13.33,67.78 13.33,55.08 13.97,54.45 13.97,49.37 11.43,46.82 11.43,41.74 10.79,41.11 10.79,39.2 IC2.20 | v31.74,81.11 31.11,80.48 v31.11,70.32 31.74,69.69 31.74,63.34 v32.38,62.7 | v52.7,79.21 52.7,65.24 v51.43,63.97 | v120.01,8.09 v120.01,15.71 v120.01,25.87 | v125.09,15.71 125.09,13.81 R12.2 | v151.76,46.19 151.12,46.82 151.12,55.71 v151.76,56.35 | R2.2 135.25,21.42 135.25,22.7 R1.2 135.25,23.96 v135.25,25.87 v135.25,27.14 | IC18.14 153.03,23.96 v153.03,27.14 153.03,44.92 154.3,46.19 IC19.16 | v10.79,13.17 10.79,15.08 IC2.11 | v23.49,13.17 23.49,15.08 IC3.11 | v36.19,13.17 36.19,15.08 IC4.11 | v48.89,13.17 48.89,15.08 IC9.11 | v61.59,13.17 61.59,15.08 IC15.11 | 62.86,44.92 62.86,48.09 61.59,49.37 61.59,55.71 SV9.19 61.59,56.98 61.59,58.25 SV9.17
  Top 0.508: 62.86,44.92 62.86,38.57 IC15.20 | v81.91,30.95 81.91,32.85 IC24.20 | v76.83,33.49 76.19,34.12 76.19,37.94 75.56,38.57 IC16.20 74.29,39.2 74.29,44.28 v74.92,44.92 | v94.61,28.41 v94.61,33.49 v94.61,36.03 v94.61,41.11 | IC20.16 102.23,39.84 v102.23,41.11 102.23,43.02 IC21.12 103.5,43.65 104.13,44.28 104.13,48.09 103.5,48.73 IC21.10 100.96,48.73 100.32,48.73 99.69,49.37 99.69,52.54 100.96,53.81 IC21.8 103.5,53.81 104.77,55.08 104.77,76.03 JP2.2 | v62.23,44.92 62.86,44.92 | v80.64,14.44 v79.37,15.71 | C10.1 97.15,27.77 97.15,24.6 99.05,22.7 v99.05,16.34 v99.05,13.81 | v32.38,45.55 v32.38,42.38 | v111.75,119.85 111.12,119.22 111.12,86.83 111.75,86.19 v111.75,81.75
  Bottom 0.508: v10.79,115.41 10.79,114.77 14.6,114.77 15.24,115.41 16.5,115.41 18.41,113.5 19.04,113.5 20.31,112.23 22.22,112.23 IC7.20 | IC8.20 36.83,112.86 36.83,113.5 43.18,113.5 44.45,114.77 v50.16,114.77 v61.59,114.77 v69.84,114.77 | v22.86,115.41 23.49,116.04 27.3,116.04 v27.93,116.67 | v36.19,122.39 v27.93,122.39 | IC23.28 159.38,119.85 146.68,119.85 IC23.1 144.14,119.85 141.6,119.85 IC29.28 139.06,119.85 126.36,119.85 IC29.1 123.82,119.85 121.28,119.85 IC22.28 118.74,119.85 v111.75,119.85 106.04,119.85 IC22.1 | IC12.20 75.56,112.23 76.83,112.23 78.1,110.96 80.64,110.96 81.91,112.23 85.72,112.23 IC13.20 87.62,112.86 90.16,112.86 90.8,113.5 93.34,113.5 94.61,112.23 98.42,112.23 IC14.20 | v130.17,69.05 141.6,69.05 IC17.35 | v151.76,69.05 154.3,69.05 IC28.16 | v151.76,71.59 144.14,71.59 IC17.36 | v114.93,79.21 116.83,79.21 R5.2 | IC25.20 77.46,78.58 78.73,78.58 79.37,77.94 83.18,77.94 85.72,75.4 99.05,75.4 100.32,76.67 104.13,76.67 JP2.2 106.04,76.67 | 106.04,76.67 116.83,76.67 R8.2 | 106.04,76.67 105.41,76.67 | v122.55,63.97 126.36,63.97 IC17.8 | v121.91,74.13 118.1,74.13 R6.2 | 22.22,39.84 12.06,39.84 11.43,39.2 IC2.20 | 22.22,39.84 22.86,39.2 IC3.20 | 22.22,39.84 34.92,39.84 35.55,39.2 IC4.20 | v48.89,43.02 48.26,42.38 v36.19,42.38 v32.38,42.38 | v13.97,79.21 18.41,79.21 20.31,81.11 IC5.24 | v31.74,81.11 32.38,81.75 42.54,81.75 IC1.24 | v13.97,70.32 v31.11,70.32 | v52.7,79.21 55.24,79.21 IC26.20 | v51.43,63.97 50.16,62.7 v32.38,62.7 | R12.2 125.72,13.17 126.99,13.17 R3.2 | v120.01,8.09 121.91,8.09 R9.2 | v125.09,15.71 123.82,15.71 IC27.10 121.28,15.71 v120.01,15.71 117.47,15.71 115.56,17.61 IC27.4 113.66,18.25 111.12,18.25 109.85,16.98 107.94,16.98 105.41,14.44 99.69,14.44 v99.05,13.81
  Bottom 0.508: v151.76,46.19 154.3,46.19 IC19.16 | v151.76,56.35 149.22,56.35 IC28.6 | v135.25,25.87 123.82,25.87 IC27.14 121.28,25.87 v120.01,25.87 | v135.25,27.14 v153.03,27.14 | v10.79,13.17 v23.49,13.17 v36.19,13.17 37.46,13.17 38.1,13.81 41.91,13.81 42.54,13.17 v48.89,13.17 v61.59,13.17 67.94,13.17 69.21,14.44 73.02,14.44 73.66,15.08 IC16.11 75.56,15.71 v79.37,15.71 | v81.91,30.95 80,30.95 R14.2 | v76.83,33.49 80.64,33.49 IC24.20 83.18,33.49 v94.61,33.49 | v94.61,28.41 96.52,28.41 C10.1 | v94.61,36.03 95.88,36.03 IC24.22 | v102.23,41.11 98.42,41.11 IC24.24 95.88,41.11 v94.61,41.11 | v74.92,44.92 74.29,45.55 62.86,45.55 v62.23,44.92 61.59,44.28 55.24,44.28 53.34,46.19 32.38,46.19 v32.38,45.55 | v80.64,14.44 81.27,15.08 86.99,15.08 87.62,15.71 98.42,15.71 v99.05,16.34 | v111.75,81.75 114.3,81.75 R7.2
VMA
  Bottom 0.254: IC18.9 154.3,10.63 161.28,10.63 163.82,13.17 163.82,70.32 130.81,70.32 129.53,71.59 128.9,71.59 IC17.5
